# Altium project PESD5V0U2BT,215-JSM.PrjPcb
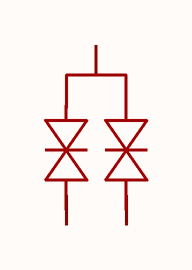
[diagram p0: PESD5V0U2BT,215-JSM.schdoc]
1 sheet, 1 parts. Net scope: global (net labels, ports and power ports of the same name join across sheets).

## Sheet PESD5V0U2BT,215-JSM.schdoc
size 127 x 101 mm

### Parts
D?  pesd5v0u2bt,215-jsm  [SOT-23-3_L2.9-W1.3-P1.90-LS2.4-BR]  (value not drawn)

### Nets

Not connected (* = marked no-connect by the designer): D? 1 2 3

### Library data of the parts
D? = pesd5v0u2bt,215-jsm: 极性:-;反向截止电压(Vrwm):5V;钳位电压:20V;峰值脉冲电流(Ipp):20A@8/20us;峰值脉冲功率(Ppp):350W@8/20us;击穿电压(VBR):8.3V;; Manufacturer: JSMSEMI(杰盛微); AddInBom: yes; ModelId: c62791f0466c4ae2a892c056b845b0ca; ModelName: SOT-23-3P_L2.9-W1.3-H1.0-LS2.4-P0.95; ModelTransform: 98.425,114.173,0,180,0,0,0.0005,-0.0005,0; Reverse Stand-Off Voltage (Vrwm): 5V; Clamping Voltage: 20V; Voltage - Breakdown: 8.3V; Reverse Leakage Current (Ir): 100nA; Number of Channels: 双路; level of protection: IEC 61000-4-2; Type: ESD; Junction Capacitance: 39pF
